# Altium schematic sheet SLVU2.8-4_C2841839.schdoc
size 127 x 101 mm
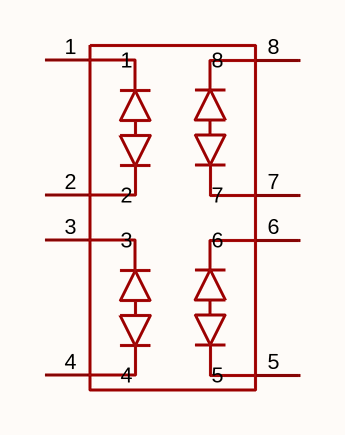
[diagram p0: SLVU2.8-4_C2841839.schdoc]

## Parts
D?  slvu2.8-4_c2841839  [SOIC-8_L4.9-W3.9-P1.27-LS6.0-BL]  (value not drawn)

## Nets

Not connected (* = marked no-connect by the designer): D? 1 2 3 4 5 6 7 8

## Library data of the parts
D? = slvu2.8-4_c2841839: 极性:单向;反向截止电压(Vrwm):2.8V;钳位电压:10V;峰值脉冲电流(Ipp):10A;峰值脉冲功率(Ppp):100W;击穿电压:4.3V;; Manufacturer: TECH PUBLIC(台舟); AddInBom: yes; ModelId: e81d2f7d937b4a6ab1dca543ff5d56a4; ModelName: SOIC-8_L4.9-W3.9-H1.7-LS6.0-P1.27; ModelTransform: 192.913,236.22,0,0,0,0,0,0,0; Polarity: 单向; Reverse Stand-Off Voltage (Vrwm): 2.8V; Clamping Voltage: 10V; Peak Pulse Current (Ipp): 10A; Peak Pulse Power Dissipation (Ppp): 100W; Voltage - Breakdown: 4.3V; Reverse Leakage Current (Ir): 1uA; Number of Channels: 四路; level of protection: IEC 61000-4-4；IEC 61000-4-5；IEC 61000-4-2; Type: ESD; Junction Capacitance: 4.7pF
